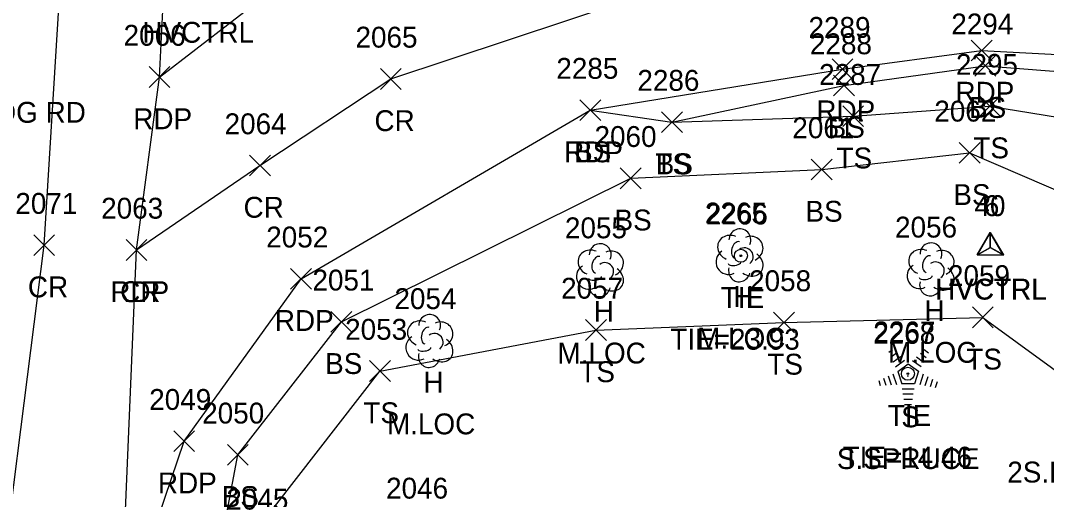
# Model space of a CAD drawing. Extents: x 1461855 to 1464118, y 556196 to 557441.
# Drawn here: x 1461940.8 to 1462039.2, y 556402.7 to 556448.6 of the extents above; entities that cross this region are included whole.
import ezdxf

# ---------------------------------------------------------------- set-up
doc = ezdxf.new("R2010")
doc.units = 0
for name, color, linetype in [('C_A', 7, 'Continuous'), ('C_C', 7, 'Continuous'), ('C_I', 7, 'Continuous'), ('CBP', 7, 'Continuous'), ('CPSM', 7, 'Continuous'), ('L_A', 7, 'Continuous'), ('L_C', 7, 'Continuous'), ('L_I', 7, 'Continuous'), ('L_TIC', 7, 'Continuous'), ('LELB', 7, 'Continuous'), ('LTC', 7, 'Continuous'), ('LTD', 7, 'Continuous'), ('P_A', 7, 'Continuous'), ('P_I', 7, 'Continuous'), ('P_TIC', 7, 'Continuous'), ('PET', 7, 'Continuous'), ('PRC', 7, 'Continuous'), ('S_C', 7, 'Continuous')]:
    doc.layers.add(name, color=color, linetype=linetype)

msp = doc.modelspace()

# ---------------------------------------------------------------- linework, layer by layer
at = {"layer": 'CBP'}
for centre, radius in [((1462009.935, 556426.064), 0.625), ((1462009.935, 556426.064), 0.0833), ((1462025.946, 556414.764), 0.625), ((1462025.946, 556414.764), 0.0833)]:
    msp.add_circle(centre, radius, dxfattribs=at)
at = {"layer": 'CPSM'}
for p, q in [((1462032.6, 556426.145), (1462033.85, 556428.31)), ((1462032.6, 556426.145), (1462033.85, 556428.31)), ((1462032.633, 556426.145), (1462033.883, 556428.31)), ((1462035.1, 556426.145), (1462033.85, 556428.31)), ((1462033.85, 556426.866), (1462033.85, 556428.31)), ((1462035.1, 556426.145), (1462033.85, 556428.31)), ((1462033.85, 556426.866), (1462033.85, 556428.31)), ((1462035.133, 556426.145), (1462033.883, 556428.31)), ((1462033.883, 556426.866), (1462033.883, 556428.31)), ((1462032.6, 556426.145), (1462033.85, 556426.866)), ((1462032.6, 556426.145), (1462033.85, 556426.866)), ((1462032.633, 556426.145), (1462033.883, 556426.866)), ((1462033.85, 556426.866), (1462033.85, 556426.866)), ((1462033.85, 556426.866), (1462035.1, 556426.145)), ((1462033.85, 556426.866), (1462033.85, 556426.866)), ((1462033.85, 556426.866), (1462035.1, 556426.145)), ((1462033.883, 556426.866), (1462033.883, 556426.866)), ((1462033.883, 556426.866), (1462035.133, 556426.145)), ((1462032.6, 556426.145), (1462035.1, 556426.145)), ((1462032.6, 556426.145), (1462035.1, 556426.145)), ((1462032.633, 556426.145), (1462035.133, 556426.145))]:
    msp.add_line(p, q, dxfattribs=at)
at = {"layer": 'L_TIC'}
for points in [[(1462032.369, 556443.277), (1462034.369, 556445.277)], [(1462034.369, 556443.277), (1462032.369, 556445.277)], [(1462018.812, 556441.377), (1462020.812, 556443.377)], [(1462020.812, 556441.377), (1462018.812, 556443.377)], [(1462032.817, 556439.405), (1462034.817, 556441.405)], [(1462034.817, 556439.405), (1462032.817, 556441.405)], [(1461994.494, 556439.023), (1461996.494, 556441.023)], [(1461996.494, 556439.023), (1461994.494, 556441.023)], [(1462019.694, 556438.438), (1462021.694, 556440.438)], [(1462021.694, 556438.438), (1462019.694, 556440.438)], [(1462002.322, 556437.872), (1462004.322, 556439.872)], [(1462004.322, 556437.872), (1462002.322, 556439.872)], [(1462002.322, 556437.872), (1462004.322, 556439.872)], [(1462004.322, 556437.872), (1462002.322, 556439.872)], [(1462030.866, 556434.925), (1462032.866, 556436.925)], [(1462032.866, 556434.925), (1462030.866, 556436.925)], [(1462016.685, 556433.326), (1462018.685, 556435.326)], [(1462018.685, 556433.326), (1462016.685, 556435.326)], [(1461998.369, 556432.491), (1462000.369, 556434.491)], [(1462000.369, 556432.491), (1461998.369, 556434.491)], [(1461998.369, 556432.491), (1462000.369, 556434.491)], [(1462000.369, 556432.491), (1461998.369, 556434.491)], [(1461970.618, 556418.735), (1461972.618, 556420.735)], [(1461972.618, 556418.735), (1461970.618, 556420.735)], [(1462013.058, 556418.672), (1462015.058, 556420.672)], [(1462015.058, 556418.672), (1462013.058, 556420.672)], [(1462032.137, 556419.161), (1462034.137, 556421.161)], [(1462034.137, 556419.161), (1462032.137, 556421.161)], [(1461995.03, 556417.951), (1461997.03, 556419.951)], [(1461997.03, 556417.951), (1461995.03, 556419.951)], [(1461995.03, 556417.951), (1461997.03, 556419.951)], [(1461997.03, 556417.951), (1461995.03, 556419.951)], [(1461974.318, 556414.015), (1461976.318, 556416.015)], [(1461976.318, 556414.015), (1461974.318, 556416.015)], [(1461960.696, 556405.988), (1461962.696, 556407.988)], [(1461962.696, 556405.988), (1461960.696, 556407.988)]]:
    msp.add_lwpolyline(points, dxfattribs=at)
at = {"layer": 'LELB'}
for points in [[(1461995.494, 556440.023), (1462003.322, 556438.872), (1462019.812, 556442.377), (1462033.369, 556444.277), (1462048.586, 556443.076), (1462058.168, 556441.152)], [(1462003.322, 556438.872), (1462020.694, 556439.438), (1462033.817, 556440.405), (1462050.902, 556437.629), (1462061.152, 556433.474)], [(1461999.369, 556433.491), (1462017.685, 556434.326), (1462031.866, 556435.925), (1462044.262, 556430.588)], [(1461959.241, 556382.278), (1461959.323, 556394.419), (1461961.696, 556406.988), (1461971.618, 556419.735), (1461999.369, 556433.491)], [(1461996.03, 556418.951), (1462014.058, 556419.672), (1462033.137, 556420.161), (1462043.004, 556412.961), (1462051.364, 556399.818), (1462043.664, 556396.808), (1462042.255, 556379.665), (1462042.956, 556370.973)], [(1461940.925, 556304.124), (1461947.098, 556342.423), (1461951.526, 556371.566), (1461953.929, 556383.668), (1461959.323, 556394.419), (1461975.318, 556415.015), (1461996.03, 556418.951)]]:
    msp.add_lwpolyline(points, dxfattribs=at)
at = {"layer": 'LTC'}
for p, q in [((1462024.119, 556416.834), (1462024.474, 556417.091)), ((1462024.329, 556416.368), (1462024.858, 556416.753)), ((1462027.146, 556416.726), (1462027.696, 556416.327)), ((1462027.517, 556417.074), (1462027.937, 556416.77)), ((1462024.538, 556415.903), (1462025.242, 556416.414)), ((1462024.748, 556415.437), (1462025.626, 556416.075)), ((1462024.972, 556414.982), (1462025.984, 556415.716)), ((1462025.984, 556415.716), (1462026.981, 556414.991)), ((1462026.404, 556416.029), (1462027.214, 556415.44)), ((1462026.775, 556416.378), (1462027.454, 556415.884)), ((1462024.518, 556414.763), (1462024.849, 556413.743)), ((1462024.972, 556414.982), (1462025.359, 556413.788)), ((1462026.981, 556414.991), (1462026.59, 556413.788)), ((1462027.419, 556414.72), (1462027.081, 556413.681)), ((1462023.152, 556414.113), (1462023.304, 556413.645)), ((1462023.607, 556414.33), (1462023.819, 556413.678)), ((1462024.062, 556414.546), (1462024.334, 556413.711)), ((1462026.59, 556413.788), (1462025.359, 556413.788)), ((1462027.863, 556414.47), (1462027.576, 556413.585)), ((1462028.308, 556414.22), (1462028.071, 556413.49)), ((1462028.752, 556413.97), (1462028.565, 556413.395)), ((1462026.552, 556413.288), (1462025.407, 556413.288)), ((1462026.468, 556412.788), (1462025.479, 556412.788)), ((1462026.384, 556412.288), (1462025.552, 556412.288)), ((1462026.3, 556411.788), (1462025.625, 556411.788))]:
    msp.add_line(p, q, dxfattribs=at)
at = {"layer": 'LTD'}
for p, q in [((1462009.787, 556426.16), (1462009.787, 556426.16)), ((1462009.787, 556426.16), (1462009.787, 556426.16)), ((1461996.398, 556424.741), (1461996.398, 556424.741)), ((1461996.398, 556424.741), (1461996.398, 556424.741)), ((1462028.111, 556424.81), (1462028.111, 556424.81)), ((1462028.111, 556424.81), (1462028.111, 556424.81)), ((1461980.046, 556417.954), (1461980.046, 556417.954)), ((1461980.046, 556417.954), (1461980.046, 556417.954))]:
    msp.add_line(p, q, dxfattribs=at)
for centre in [(1462009.833, 556427.594), (1461996.445, 556426.175), (1462028.158, 556426.244), (1461980.092, 556419.388)]:
    msp.add_arc(centre, 1.047, 335.52715, 180.95627, dxfattribs=at)
for centre, major_axis, ratio, start_param, end_param in [((1462008.995, 556426.826), (1.21, -0.512), 0.895232, 1.570796, 4.712389), ((1462009.578, 556426.618), (-0.208, -0.792), 0.645439, 3.141593, 6.283185), ((1462010.828, 556426.743), (-1.141, -0.483), 0.949671, 1.570796, 4.712389), ((1461995.606, 556425.408), (1.21, -0.512), 0.895232, 1.570796, 4.712389), ((1461997.439, 556425.325), (-1.141, -0.483), 0.949671, 1.570796, 4.712389), ((1462008.703, 556425.451), (0.584, -1.042), 0.959034, 3.141593, 6.283185), ((1462010.287, 556425.993), (-0.5, 0.667), 0.989748, 3.141593, 6.283185), ((1462027.319, 556425.476), (1.21, -0.512), 0.895232, 1.570796, 4.712389), ((1462029.152, 556425.393), (-1.141, -0.483), 0.949671, 1.570796, 4.712389), ((1461996.189, 556425.2), (-0.208, -0.792), 0.645439, 3.141593, 6.283185), ((1461996.898, 556424.575), (-0.5, 0.667), 0.989748, 3.141593, 6.283185), ((1462009.328, 556425.409), (-0.625, -0.083), 0.423636, 0, 3.141593), ((1462010.787, 556425.326), (-1.09, 0.792), 0.841452, 1.570796, 4.712389), ((1462027.902, 556425.268), (-0.208, -0.792), 0.645439, 3.141593, 6.283185), ((1462028.611, 556424.643), (-0.5, 0.667), 0.989748, 3.141593, 6.283185), ((1461995.315, 556424.033), (0.584, -1.042), 0.959034, 3.141593, 6.283185), ((1461997.398, 556423.908), (-1.09, 0.792), 0.841452, 1.570796, 4.712389), ((1462009.787, 556424.66), (0.265, 1.061), 0.942809, 1.570796, 4.712389), ((1462027.028, 556424.101), (0.584, -1.042), 0.959034, 3.141593, 6.283185), ((1462029.111, 556423.976), (-1.09, 0.792), 0.841452, 1.570796, 4.712389), ((1461996.398, 556423.241), (0.265, 1.061), 0.942809, 1.570796, 4.712389), ((1461995.94, 556423.991), (-0.625, -0.083), 0.423636, 0, 3.141593), ((1462028.111, 556423.31), (0.265, 1.061), 0.942809, 1.570796, 4.712389), ((1462027.653, 556424.059), (-0.625, -0.083), 0.423636, 0, 3.141593), ((1461979.254, 556418.62), (1.21, -0.512), 0.895232, 1.570796, 4.712389), ((1461981.087, 556418.537), (-1.141, -0.483), 0.949671, 1.570796, 4.712389), ((1461979.837, 556418.412), (-0.208, -0.792), 0.645439, 3.141593, 6.283185), ((1461980.546, 556417.787), (-0.5, 0.667), 0.989748, 3.141593, 6.283185), ((1461978.962, 556417.245), (0.584, -1.042), 0.959034, 3.141593, 6.283185), ((1461981.046, 556417.121), (-1.09, 0.792), 0.841452, 1.570796, 4.712389), ((1461980.046, 556416.454), (0.265, 1.061), 0.942809, 1.570796, 4.712389), ((1461979.587, 556417.204), (-0.625, -0.083), 0.423636, 0, 3.141593)]:
    msp.add_ellipse(centre, major_axis=major_axis, ratio=ratio, start_param=start_param, end_param=end_param, dxfattribs=at)
at = {"layer": 'P_TIC'}
for points in [[(1462032.021, 556444.734), (1462034.021, 556446.734)], [(1462034.021, 556444.734), (1462032.021, 556446.734)], [(1461953.173, 556442.192), (1461955.173, 556444.192)], [(1461955.173, 556442.192), (1461953.173, 556444.192)], [(1461953.173, 556442.192), (1461955.173, 556444.192)], [(1461955.173, 556442.192), (1461953.173, 556444.192)], [(1462018.682, 556442.946), (1462020.682, 556444.946)], [(1462020.682, 556442.946), (1462018.682, 556444.946)], [(1461975.359, 556442.012), (1461977.359, 556444.012)], [(1461977.359, 556442.012), (1461975.359, 556444.012)], [(1461994.494, 556439.023), (1461996.494, 556441.023)], [(1461996.494, 556439.023), (1461994.494, 556441.023)], [(1461962.807, 556433.71), (1461964.807, 556435.71)], [(1461964.807, 556433.71), (1461962.807, 556435.71)], [(1461942.124, 556426.083), (1461944.124, 556428.083)], [(1461944.124, 556426.083), (1461942.124, 556428.083)], [(1461950.969, 556425.622), (1461952.969, 556427.622)], [(1461952.969, 556425.622), (1461950.969, 556427.622)], [(1461950.969, 556425.622), (1461952.969, 556427.622)], [(1461952.969, 556425.622), (1461950.969, 556427.622)], [(1461966.75, 556422.86), (1461968.75, 556424.86)], [(1461968.75, 556422.86), (1461966.75, 556424.86)], [(1461955.538, 556407.295), (1461957.538, 556409.295)], [(1461957.538, 556407.295), (1461955.538, 556409.295)]]:
    msp.add_lwpolyline(points, dxfattribs=at)
at = {"layer": 'PET'}
for points in [[(1461935.994, 556304.706), (1461941.55, 556343.697), (1461948.694, 556384.516), (1461950.446, 556390.309), (1461951.969, 556426.622), (1461954.173, 556443.192), (1461955.345, 556466.861), (1461956.954, 556490.651)], [(1461954.173, 556443.192), (1461968.123, 556453.952), (1461978.771, 556459.457)], [(1461950.446, 556390.309), (1461956.538, 556408.295), (1461967.75, 556423.86), (1461995.494, 556440.023), (1462019.682, 556443.946), (1462033.021, 556445.734), (1462048.811, 556444.893)]]:
    msp.add_lwpolyline(points, dxfattribs=at)
at = {"layer": 'PRC'}
for points in [[(1461925.455, 556305.981), (1461931.482, 556345.963), (1461937.931, 556386.439), (1461943.124, 556427.083), (1461945.493, 556465.379), (1461946.96, 556493.016), (1461948.287, 556523.837), (1461949.597, 556552.436), (1461949.092, 556575.708), (1461945.132, 556594.535), (1461941.155, 556612.685), (1461941.736, 556618.093), (1461960.038, 556581.267), (1461976.525, 556548.035), (1461990.309, 556523.955), (1462006.117, 556501.89), (1462023.427, 556483.274), (1462041.849, 556469.086), (1462061.758, 556457.443), (1462082.723, 556450.203), (1462107.816, 556443.977), (1462129.573, 556440.387), (1462147.933, 556438.199)], [(1461951.969, 556426.622), (1461963.807, 556434.71), (1461976.359, 556443.012), (1462016.097, 556456.217), (1462030.094, 556457.862)]]:
    msp.add_lwpolyline(points, dxfattribs=at)

# ---------------------------------------------------------------- texts
at = {"layer": 'C_A'}
for s, p in [('HVCTRL', (1461952.547, 556446.479)), ('HVCTRL', (1462028.543, 556421.866)), ('HVCTRL', (1462028.543, 556421.866)), ('HVCTRL', (1462028.576, 556421.866)), ('TIE', (1462008.013, 556421.064)), ('TIE', (1462024.025, 556409.764))]:
    msp.add_text(s, height=2, dxfattribs=at).set_placement(p)
at = {"layer": 'C_C'}
for s, p in [('TIE=23.93', (1462003.163, 556417.064)), ('TIE=14.46', (1462019.687, 556405.764))]:
    msp.add_text(s, height=2, dxfattribs=at).set_placement(p)
at = {"layer": 'C_I'}
for s, p in [('40', (1462032.332, 556429.866)), ('6', (1462033.228, 556429.866)), ('6', (1462033.228, 556429.866)), ('2266', (1462006.572, 556429.064)), ('2267', (1462022.639, 556417.764))]:
    msp.add_text(s, height=2, dxfattribs=at).set_placement(p)
at = {"layer": 'L_A'}
for s, p in [('BS', (1462031.81, 556439.277)), ('BS', (1462018.253, 556437.377)), ('TS', (1462032.227, 556435.405)), ('BS', (1461993.935, 556435.023)), ('TS', (1462019.103, 556434.438)), ('TS', (1462001.731, 556433.872)), ('BS', (1462001.763, 556433.872)), ('BS', (1462030.307, 556430.925)), ('BS', (1462016.126, 556429.326)), ('BS', (1461997.81, 556428.491)), ('BS', (1461997.81, 556428.491)), ('H', (1462009.22, 556421.16)), ('H', (1461995.831, 556419.741)), ('H', (1462027.544, 556419.81)), ('BS', (1461970.059, 556414.735)), ('TS', (1462012.467, 556414.672)), ('TS', (1462031.547, 556415.161)), ('TS', (1461994.44, 556413.951)), ('TS', (1461994.44, 556413.951)), ('H', (1461979.479, 556412.954)), ('TS', (1461973.727, 556410.015)), ('S', (1462025.31, 556409.626)), ('BS', (1461960.137, 556401.988))]:
    msp.add_text(s, height=2, dxfattribs=at).set_placement(p)
at = {"layer": 'L_C'}
for s, p in [('M.LOC', (1462005.731, 556417.16)), ('M.LOC', (1461992.343, 556415.741)), ('M.LOC', (1462024.056, 556415.81)), ('M.LOC', (1461975.99, 556408.954)), ('S.SPRUCE', (1462019.136, 556405.626)), ('2S.BUCK THORN', (1462035.479, 556404.337))]:
    msp.add_text(s, height=2, dxfattribs=at).set_placement(p)
at = {"layer": 'L_I'}
for s, p in [('2294', (1462030.109, 556447.277)), ('2288', (1462016.552, 556445.377)), ('2295', (1462030.557, 556443.405)), ('2285', (1461992.234, 556443.023)), ('2287', (1462017.434, 556442.438)), ('2286', (1462000.007, 556441.872)), ('2286', (1462000.007, 556441.872)), ('2062', (1462028.48, 556438.925)), ('2061', (1462014.866, 556437.326)), ('2060', (1461995.897, 556436.491)), ('2060', (1461995.897, 556436.491)), ('2265', (1462006.479, 556429.16)), ('2055', (1461993.059, 556427.741)), ('2056', (1462024.717, 556427.81)), ('2051', (1461968.846, 556422.735)), ('2058', (1462010.719, 556422.672)), ('2059', (1462029.791, 556423.161)), ('2057', (1461992.692, 556421.951)), ('2057', (1461992.692, 556421.951)), ('2054', (1461976.707, 556420.954)), ('2053', (1461971.979, 556418.015)), ('2268', (1462022.617, 556417.626)), ('2050', (1461958.271, 556409.988)), ('2046', (1461975.906, 556402.794)), ('2046', (1461975.906, 556402.794)), ('2045', (1461960.589, 556401.739))]:
    msp.add_text(s, height=2, dxfattribs=at).set_placement(p)
at = {"layer": 'LTC'}
msp.add_text('.', height=1.037, rotation=270, dxfattribs=at).set_placement((1462025.867, 556414.73))
at = {"layer": 'P_A'}
for s, p in [('RDP', (1462030.509, 556440.734)), ('RDP', (1461951.661, 556438.192)), ('RDP', (1461951.661, 556438.192)), ('RDP', (1462017.17, 556438.946)), ('CR', (1461974.792, 556438.012)), ('RDP', (1461992.982, 556435.023)), ('CR', (1461962.24, 556429.71)), ('CR', (1461941.557, 556422.083)), ('RDP', (1461949.458, 556421.622)), ('CR', (1461950.402, 556421.622)), ('RDP', (1461965.238, 556418.86)), ('RDP', (1461954.026, 556403.295))]:
    msp.add_text(s, height=2, dxfattribs=at).set_placement(p)
at = {"layer": 'P_I'}
for s, p in [('2066', (1461950.732, 556446.192)), ('2066', (1461950.732, 556446.192)), ('2289', (1462016.415, 556446.946)), ('2065', (1461972.974, 556446.012)), ('2285', (1461992.234, 556443.023)), ('2064', (1461960.421, 556437.71)), ('2071', (1461940.353, 556430.083)), ('2063', (1461948.584, 556429.622)), ('2063', (1461948.584, 556429.622)), ('2052', (1461964.411, 556426.86)), ('2049', (1461953.191, 556411.295))]:
    msp.add_text(s, height=2, dxfattribs=at).set_placement(p)
at = {"layer": 'S_C'}
msp.add_text('STOP & PULP MILL BRDG RD', height=2, dxfattribs=at).set_placement((1461909.812, 556438.811))

doc.saveas('drawing.dxf')
